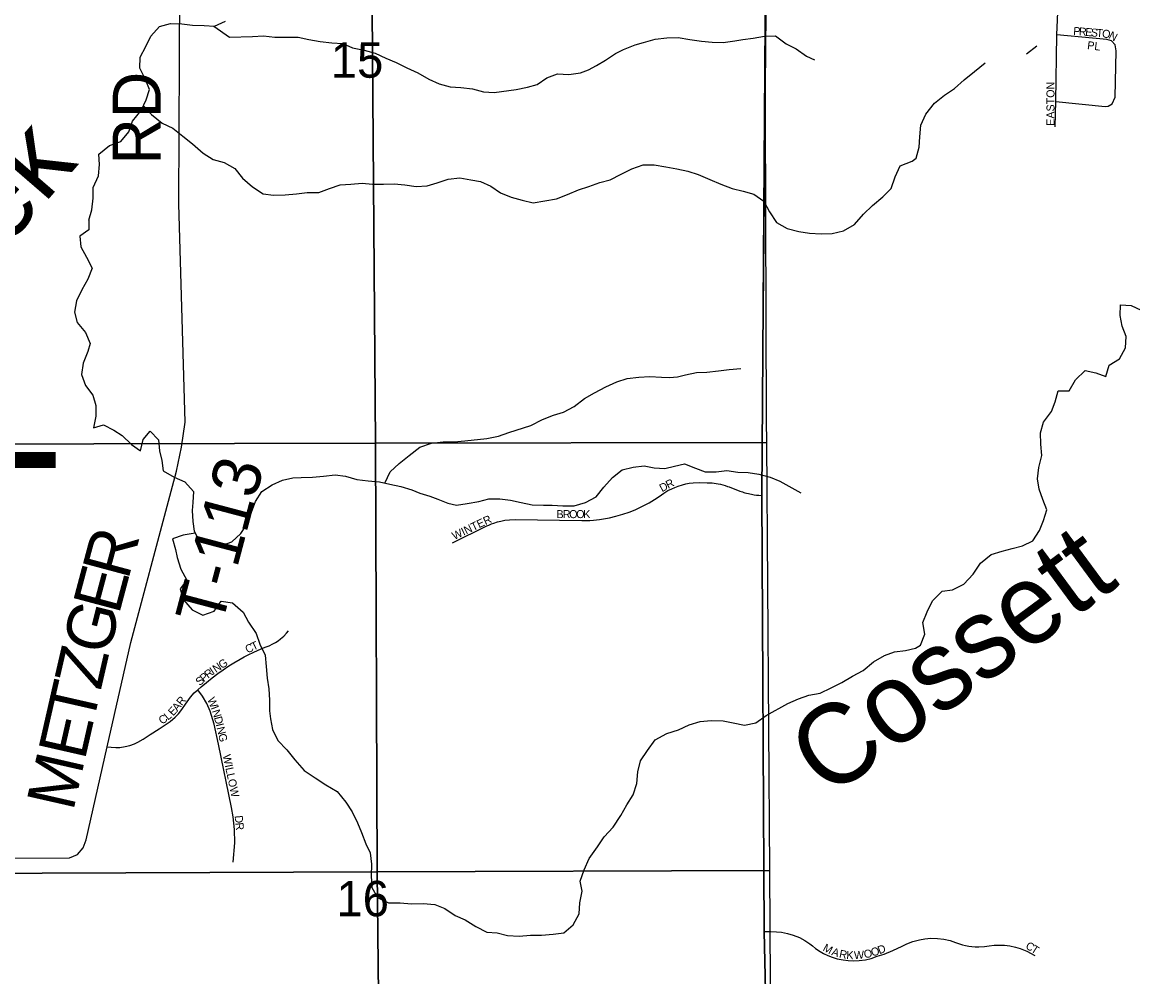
# Model space of a CAD drawing. Extents: x 1985906 to 2277390, y 930619 to 1324581.
# Drawn here: x 2134931 to 2141868, y 1173843 to 1179804 of the extents above; entities that cross this region are included whole.
import ezdxf

# ---------------------------------------------------------------- set-up
doc = ezdxf.new("R2010")
doc.units = 0
for name, color, linetype in [('GM_X_County_Road', 7, 'Continuous'), ('GM_X_Minor_River', 7, 'Continuous'), ('GM_X_Minor_River_Text', 7, 'Continuous'), ('GM_X_Section', 7, 'Continuous'), ('GM_X_Section_Text', 7, 'Continuous'), ('GM_X_Township', 7, 'Continuous'), ('GM_X_Township_Road', 7, 'Continuous'), ('GM_X_Township_Road_Text', 7, 'Continuous'), ('GM_X_Township_Subdivision', 7, 'Continuous'), ('GM_X_Township_Subdivision_Text', 7, 'Continuous'), ('GM_X_Township_Text', 7, 'Continuous')]:
    doc.layers.add(name, color=color, linetype=linetype)

msp = doc.modelspace()

# ---------------------------------------------------------------- linework, layer by layer
at = {"layer": 'GM_X_County_Road'}
msp.add_lwpolyline([(2139668, 1166481.9), (2139668.5, 1166493.7), (2139656.8, 1167688.3), (2139644.7, 1169748.4), (2139611.5, 1172078.9), (2139566.5, 1174124.8), (2139551.5, 1176849.1), (2139580.5, 1180100.5)], dxfattribs=at)
at = {"layer": 'GM_X_Minor_River'}
for points in [[(2135347, 1178568.7), (2135365.4, 1178633), (2135373.8, 1178705.2), (2135374.1, 1178771.5), (2135408.6, 1178843.6), (2135415, 1178915.9), (2135409.3, 1178980.2), (2135475.7, 1179034.1), (2135548.1, 1179059.8), (2135596.5, 1179119.8), (2135620.9, 1179186), (2135675.4, 1179252), (2135705.8, 1179320.1), (2135726.2, 1179384.3), (2135698.4, 1179450.7), (2135666.7, 1179517.2), (2135669, 1179585.5), (2135703.5, 1179651.6), (2135733.9, 1179717.7), (2135788.3, 1179777.7), (2135858.6, 1179795.4), (2135928.8, 1179793), (2135994.9, 1179784.6), (2136067.1, 1179784.2), (2136133.3, 1179779.8), (2136201.6, 1179809.5)], [(2136128.8, 1179779.1), (2136225.2, 1179711), (2136369.6, 1179714.2), (2136437.9, 1179719.8), (2136510, 1179711.4), (2136654.4, 1179710.6), (2136722.5, 1179696.2), (2136792.7, 1179683.7), (2136864.8, 1179675.3), (2136933, 1179670.9), (2136995, 1179644.4), (2137067.2, 1179630), (2137135.3, 1179611.5), (2137203.3, 1179579), (2137267.3, 1179552.5), (2137333.4, 1179520), (2137401.4, 1179487.5), (2137471.4, 1179449), (2137535.4, 1179418.5), (2137603.5, 1179400), (2137671.7, 1179395.6), (2137743.9, 1179387.2), (2137812, 1179368.7), (2137880.1, 1179364.3), (2138016.6, 1179383.7), (2138086.9, 1179397.3), (2138147.1, 1179415.1), (2138207.5, 1179456.9), (2138273.8, 1179480.7), (2138346, 1179478.3), (2138418.3, 1179487.9), (2138468.5, 1179505.7), (2138518.8, 1179533.6), (2138575.1, 1179567.4), (2138637.5, 1179609.2), (2138687.7, 1179633.1), (2138760.1, 1179662.8), (2138812.3, 1179676.6), (2138884.6, 1179698.3), (2138956.8, 1179705.9), (2139029.1, 1179707.5), (2139101.2, 1179695.1), (2139173.3, 1179684.6), (2139241.5, 1179680.2), (2139309.7, 1179677.8), (2139381.9, 1179687.5), (2139432.1, 1179695.2), (2139496.4, 1179704.9), (2139568.6, 1179716.6), (2139636.8, 1179718.2), (2139702.8, 1179669.6), (2139764.8, 1179637.2), (2139830.7, 1179592.6), (2139880.7, 1179568.2)], [(2141269.4, 1179654.7), (2141203.4, 1179604.5)], [(2140489.6, 1178936.4), (2140514.2, 1178954.5), (2140534.2, 1179022.7), (2140538.1, 1179088.8), (2140544, 1179161), (2140576, 1179229.1), (2140629.9, 1179297.3), (2140691.8, 1179347.5), (2140753.8, 1179389.7), (2140813.7, 1179443.8), (2140879.6, 1179496), (2140945.6, 1179550.2)], [(2135687.6, 1179284.1), (2135739.4, 1179227.5), (2135805.4, 1179172.9), (2135871.4, 1179142.4), (2135935.3, 1179091.8), (2135995.3, 1179045.3), (2136061.2, 1178986.7), (2136123.1, 1178946.2), (2136193.2, 1178927.7), (2136259.2, 1178891.2), (2136307.1, 1178830.6), (2136369, 1178776.1), (2136436.9, 1178731.5), (2136501.1, 1178723.1), (2136573.3, 1178726.7), (2136645.5, 1178732.3), (2136711.7, 1178740), (2136783.9, 1178739.6), (2136850.3, 1178765.4), (2136916.6, 1178789.1), (2136984.8, 1178792.8), (2137055, 1178798.4), (2137119.1, 1178792), (2137187.3, 1178791.6), (2137255.5, 1178795.3), (2137321.7, 1178788.9), (2137391.8, 1178778.4), (2137460, 1178782.1), (2137522.3, 1178799.8), (2137592.6, 1178823.5), (2137664.9, 1178831.2), (2137733, 1178818.7), (2137793.1, 1178808.4), (2137859.2, 1178779.9), (2137919.1, 1178737.4), (2137985.2, 1178710.9), (2138053.3, 1178692.4), (2138123.4, 1178676), (2138195.6, 1178687.6), (2138267.9, 1178701.3), (2138338.2, 1178727), (2138406.6, 1178756.8), (2138470.9, 1178778.5), (2138539.2, 1178802.2), (2138603.4, 1178819.9), (2138671.8, 1178855.7), (2138738.2, 1178887.5), (2138810.5, 1178913.2), (2138878.7, 1178912.8), (2138950.8, 1178900.4), (2139021, 1178888), (2139089.1, 1178873.5), (2139153.2, 1178853.1), (2139225.2, 1178822.5), (2139295.2, 1178792), (2139365.3, 1178765.5), (2139433.4, 1178749.1), (2139501.5, 1178730.6), (2139563.5, 1178686.1), (2139599.2, 1178619.6), (2139643, 1178553.1), (2139709, 1178516.5), (2139781.1, 1178496.1), (2139849.3, 1178485.6), (2139921.5, 1178483.2), (2139989.7, 1178484.8), (2140061.9, 1178500.5), (2140130.3, 1178540.3), (2140186.8, 1178604.3), (2140241.2, 1178660.2), (2140305.7, 1178714.1), (2140358.1, 1178766.1), (2140384.5, 1178838.2), (2140415, 1178906.4), (2140489.6, 1178936.4)], [(2135347.1, 1178568.8), (2135346.8, 1178506.5), (2135290.4, 1178468.6), (2135298.1, 1178400.3), (2135333.9, 1178335.8), (2135367.6, 1178267.3), (2135341.2, 1178199.2), (2135304.8, 1178133.1), (2135270.3, 1178063), (2135258, 1177992.7), (2135275.7, 1177928.3), (2135327.5, 1177865.8), (2135355.3, 1177797.3), (2135341, 1177747.2), (2135312.5, 1177675), (2135302.1, 1177604.8), (2135325.9, 1177536.3), (2135371.7, 1177475.8), (2135391.4, 1177409.4), (2135391.1, 1177343.1), (2135376.7, 1177270.9), (2135439, 1177290.6), (2135503, 1177256.1), (2135555, 1177223.7), (2135614.8, 1177167.1), (2135670.8, 1177126.6), (2135687.2, 1177198.9), (2135731.6, 1177250.8), (2135783.5, 1177196.3), (2135789.1, 1177128), (2135802.9, 1177067.7), (2135812.6, 1177003.3), (2135880.6, 1176962.8), (2135946.6, 1176934.3), (2136000.5, 1176873.7), (2135996.1, 1176805.4), (2135993.9, 1176755.2), (2135997.5, 1176686.9), (2136005.2, 1176626.6), (2136039, 1176560.1), (2136107.1, 1176541.7), (2136175.3, 1176535.3), (2136241.6, 1176559), (2136296, 1176610.9), (2136340.4, 1176677), (2136362.8, 1176745.1), (2136389.2, 1176811.3), (2136427.7, 1176873.4), (2136492, 1176915.2), (2136556.4, 1176945), (2136622.6, 1176958.7), (2136672.8, 1176960.4), (2136745, 1176962), (2136813.2, 1176969.7), (2136885.5, 1176977.3), (2136951.6, 1176968.9), (2137021.7, 1176948.4), (2137091.8, 1176940), (2137162, 1176933.6), (2137228.1, 1176919.2), (2137296.2, 1176904.7), (2137364.3, 1176884.2), (2137414.4, 1176863.9), (2137476.5, 1176843.5), (2137526.5, 1176825.1), (2137590.6, 1176800.6), (2137644.6, 1176788.3), (2137710.9, 1176798), (2137783.1, 1176811.6), (2137845.4, 1176827.3), (2137913.6, 1176827), (2137981.7, 1176818.6), (2138047.9, 1176804.1), (2138116, 1176789.7), (2138188.2, 1176787.3), (2138242.3, 1176787), (2138308.5, 1176784.6), (2138378.7, 1176784.2), (2138449, 1176803.9), (2138515.3, 1176839.7), (2138563.8, 1176899.7), (2138618.2, 1176961.7), (2138678.6, 1177009.6), (2138746.9, 1177025.3), (2138815.1, 1177032.9), (2138879.3, 1177020.5), (2138945.4, 1177016.1), (2139005.7, 1177031.9), (2139067.9, 1177045.6), (2139136, 1177019.1), (2139198, 1176996.6), (2139266.2, 1176996.3), (2139332.4, 1177003.9), (2139400.6, 1176993.5), (2139464.7, 1176991.2), (2139532.9, 1176980.7), (2139603, 1176962.3), (2139663, 1176937.8), (2139795, 1176864.8)], [(2140510.6, 1175895.9), (2140542.9, 1175914), (2140568.8, 1175982.2), (2140556.7, 1176054.3), (2140582.7, 1176122.5), (2140616.6, 1176190.7), (2140676.5, 1176250.9), (2140742.5, 1176258.9), (2140812.4, 1176295.1), (2140870.3, 1176357.3), (2140916.3, 1176425.5), (2140984.2, 1176479.6), (2141052.2, 1176499.8), (2141114.1, 1176517.8), (2141178.1, 1176533.9), (2141244, 1176566.1), (2141286, 1176630.2), (2141309.9, 1176692.4), (2141331.8, 1176758.6), (2141305.8, 1176822.7), (2141283.7, 1176888.8), (2141271.7, 1176952.9), (2141281.6, 1177023.1), (2141299.5, 1177097.2), (2141293.5, 1177169.4), (2141291.4, 1177239.5), (2141309.4, 1177305.7), (2141359.3, 1177371.9), (2141383.2, 1177434.1), (2141401.2, 1177502.2), (2141471.1, 1177502.3), (2141509.1, 1177570.5), (2141571, 1177628.6), (2141637, 1177614.7), (2141699, 1177590.7), (2141720.9, 1177662.8), (2141784.8, 1177701), (2141822.8, 1177771.2), (2141826.7, 1177841.3), (2141800.7, 1177905.4), (2141788.6, 1177971.6), (2141790.6, 1178039.7), (2141858.5, 1178035.8), (2141920.5, 1178005.8)], [(2137196.6, 1176926), (2137230.5, 1176995.5), (2137284.9, 1177047.4), (2137347.4, 1177097.3), (2137415.8, 1177151.1), (2137488.1, 1177174.8), (2137560.4, 1177182.5), (2137628.6, 1177184.1), (2137696.8, 1177189.8), (2137833.2, 1177205.1), (2137905.5, 1177218.7), (2137971.8, 1177242.5), (2138108.4, 1177285.9), (2138180.8, 1177323.7), (2138249.1, 1177349.4), (2138311.4, 1177369.2), (2138377.8, 1177405), (2138444.2, 1177454.8), (2138506.5, 1177488.6), (2138576.9, 1177526.4), (2138645.3, 1177558.2), (2138709.6, 1177579.9), (2138781.8, 1177587.6), (2138852, 1177591.2), (2138924.2, 1177586.8), (2138974.3, 1177584.5), (2139024.5, 1177590.2), (2139074.7, 1177602), (2139143, 1177615.7), (2139207.2, 1177619.3), (2139279.4, 1177627), (2139347.6, 1177634.6), (2139419.9, 1177642.3)], [(2136012, 1176614.2), (2135936.9, 1176600.9), (2135870.6, 1176577.1), (2135888.3, 1176510.7), (2135900.1, 1176460.4), (2135921.8, 1176388), (2135959.6, 1176319.5), (2135917.2, 1176265.5), (2135938.9, 1176197.1), (2135992.8, 1176134.5), (2136058.8, 1176102), (2136131.1, 1176125.7), (2136173.5, 1176187.7), (2136245.7, 1176177.3), (2136311.6, 1176120.7), (2136345.4, 1176058.2), (2136393.1, 1175985.6), (2136414.9, 1175919.2), (2136448.6, 1175850.8), (2136454.3, 1175780.4), (2136462, 1175708), (2136471.7, 1175641.7), (2136475.3, 1175569.4), (2136475, 1175503.1), (2136482.7, 1175452.8), (2136494.4, 1175386.4), (2136528.2, 1175318), (2136584.1, 1175259.4), (2136633.9, 1175196.8), (2136691.7, 1175130.2), (2136761.7, 1175085.6), (2136827.7, 1175041.1), (2136897.7, 1175000.5), (2136953.5, 1174933.9), (2136991.3, 1174873.5), (2137025, 1174805), (2137050.8, 1174744.6), (2137078.5, 1174674.1), (2137104.3, 1174617.7), (2137114, 1174545.3), (2137111.6, 1174473), (2137115.3, 1174400.7), (2137151.1, 1174338.2), (2137219.1, 1174305.7), (2137291.3, 1174305.3), (2137363.5, 1174298.9), (2137435.7, 1174300.5), (2137507.8, 1174294.1), (2137571.9, 1174269.6), (2137635.9, 1174225.1), (2137697.9, 1174198.6), (2137763.9, 1174156.1), (2137833.9, 1174121.5), (2137898.1, 1174117.1), (2137962.2, 1174100.7), (2138034.3, 1174096.3), (2138106.6, 1174101.9), (2138174.8, 1174103.6), (2138247, 1174109.2), (2138315.2, 1174116.8), (2138371.6, 1174166.8), (2138410.1, 1174236.8), (2138414.4, 1174305.1), (2138428.8, 1174377.4), (2138417.1, 1174439.7), (2138441.5, 1174509.9), (2138472, 1174582), (2138524.5, 1174654.1), (2138566.9, 1174716.1), (2138621.4, 1174778.1), (2138669.9, 1174850.1), (2138708.3, 1174916.2), (2138746.7, 1174980.2), (2138771.1, 1175050.4), (2138775.5, 1175122.7), (2138793.9, 1175190.9), (2138836.4, 1175257), (2138884.8, 1175323), (2138957.2, 1175362.8), (2139029.5, 1175384.5), (2139097.9, 1175416.2), (2139166.2, 1175438), (2139234.4, 1175443.6), (2139308.6, 1175441.2), (2139372.7, 1175428.8), (2139442.8, 1175414.3), (2139513.1, 1175428), (2139577.5, 1175473.8), (2139714.3, 1175549.4), (2139780.6, 1175579.2), (2139844.9, 1175600.9), (2139915.2, 1175614.6), (2139983.5, 1175646.4), (2140049.9, 1175680.2), (2140116.2, 1175720), (2140184.6, 1175755.8), (2140249.1, 1175809.6), (2140317.4, 1175849.4), (2140379.7, 1175871.2), (2140448, 1175880.8), (2140510.6, 1175896)]]:
    msp.add_lwpolyline(points, dxfattribs=at)
at = {"layer": 'GM_X_Section'}
for points in [[(2137116.7, 1179878.2), (2137137.1, 1177174.3), (2134496.5, 1177169.7), (2134481.4, 1179851.9)], [(2139570, 1179882.9), (2139578.7, 1177314.5), (2139579.9, 1177178.5), (2137137.1, 1177174.3), (2137116.7, 1179878.2)], [(2137137.1, 1177174.3), (2137148.8, 1174497.5), (2134532.2, 1174488.2), (2134496.5, 1177169.7)], [(2139579.9, 1177178.5), (2139599.2, 1174506.3), (2137148.8, 1174497.5), (2137137.1, 1177174.3)], [(2137148.8, 1174497.5), (2137179.2, 1171609.7), (2134570.4, 1171622.4), (2134532.2, 1174488.2)], [(2139599.2, 1174506.3), (2139614.4, 1172069.9), (2139617.3, 1171597.8), (2137179.2, 1171609.7), (2137148.8, 1174497.5)]]:
    msp.add_lwpolyline(points, close=True, dxfattribs=at)
at = {"layer": 'GM_X_Township'}
for points in [[(2139644.7, 1169748.4), (2139611.5, 1172078.9), (2139566.5, 1174124.9), (2139551.5, 1176849.1), (2139574.3, 1180104.3), (2139561.5, 1182741.2), (2139581.4, 1183078.2), (2139560.8, 1184019.4), (2139556, 1185150.7), (2139556, 1185444), (2139503.5, 1186666), (2139494.6, 1188225.5), (2139496.8, 1188359.9), (2139502.2, 1190793.3), (2139549.1, 1193676.6), (2140581.8, 1193696.4), (2144321.2, 1193786.8), (2145028.4, 1193800.8), (2151106.9, 1193912.6)], [(2117908.3, 1193445.4), (2126053.1, 1193488.1), (2129443.2, 1193492.7), (2134076.1, 1193549.4), (2139549.1, 1193676.6), (2139502.2, 1190793.3), (2139496.8, 1188359.9), (2139494.6, 1188225.5), (2139503.5, 1186666), (2139556, 1185444), (2139556, 1185150.7), (2139560.8, 1184019.4), (2139581.4, 1183078.2), (2139561.5, 1182741.2), (2139574.3, 1180104.3), (2139551.5, 1176849.1), (2139566.5, 1174124.9), (2139611.5, 1172078.9), (2139644.7, 1169748.4)]]:
    msp.add_lwpolyline(points, dxfattribs=at)
at = {"layer": 'GM_X_Township_Road'}
for points in [[(2135277.4, 1174606.2), (2135313.1, 1174647.8), (2135330.9, 1174698.4), (2135462.8, 1175279), (2135610.5, 1175929.8), (2135845.5, 1176813.2), (2135896.1, 1177000.6), (2135925.8, 1177149.3), (2135949.6, 1177307), (2135909.4, 1178670.4), (2135915.3, 1180020.3)], [(2134376.1, 1174582.4), (2135226.8, 1174585.3), (2135277.4, 1174606.2)]]:
    msp.add_lwpolyline(points, dxfattribs=at)
at = {"layer": 'GM_X_Township_Subdivision'}
for points in [[(2141383.9, 1179150.2), (2141388, 1179309.5), (2141394.2, 1179724.1), (2141411.8, 1180148)], [(2141388, 1179309.5), (2141695.7, 1179277.9), (2141713.5, 1179280.2), (2141738.5, 1179294.5), (2141757, 1179336.5), (2141763.7, 1179625.2), (2141758.1, 1179662.6), (2141735, 1179688.1), (2141705.3, 1179696.8), (2141394.2, 1179724.1)], [(2137618.9, 1176553.3), (2137833.9, 1176658.1), (2137845.2, 1176663.4), (2137861.9, 1176670.5), (2137877.7, 1176676.4), (2137899.2, 1176683.2), (2137920.7, 1176688.7), (2137946.8, 1176693.8), (2137975.7, 1176697.3), (2138010.3, 1176698.8), (2138427.5, 1176691.3), (2138448.4, 1176691.7), (2138476.7, 1176693), (2138500.6, 1176694.8), (2138536.7, 1176698.8), (2138561.2, 1176702.4), (2138598.5, 1176709.3), (2138639.4, 1176718.8), (2138683.7, 1176731.6), (2138721.9, 1176744.8), (2138758.8, 1176759.5), (2138802.2, 1176779.3), (2138847.2, 1176803.2), (2138897.9, 1176834.4), (2138924.2, 1176852.6), (2138938.4, 1176862.5), (2138951, 1176870.5), (2138964.7, 1176878.6), (2138988.9, 1176891), (2139007.5, 1176899.2), (2139028.8, 1176907.3), (2139056.1, 1176915.6), (2139075.4, 1176920.3), (2139097.8, 1176924.5), (2139123, 1176927.6), (2139160.2, 1176929.2), (2139210.2, 1176928.4), (2139219.6, 1176928.1), (2139230.9, 1176927.5), (2139241.7, 1176926.6), (2139253.1, 1176925.4), (2139264.7, 1176923.8), (2139278.4, 1176921.4), (2139293.7, 1176918.2), (2139306.9, 1176914.9), (2139321.1, 1176910.8), (2139337.2, 1176905.5), (2139347.7, 1176901.6), (2139414, 1176876.1), (2139421.4, 1176873.4), (2139430.1, 1176870.3), (2139437.7, 1176867.9), (2139445.4, 1176865.5), (2139455.4, 1176862.7), (2139466.7, 1176859.9), (2139476.2, 1176857.8), (2139486.5, 1176855.7), (2139494.8, 1176854.4), (2139503.8, 1176853), (2139517.2, 1176851.4), (2139531.7, 1176850.2), (2139551.5, 1176849.1)], [(2135462.8, 1175279), (2135486.6, 1175275.8), (2135515.2, 1175274.4), (2135541.4, 1175275.6), (2135574.7, 1175280.4), (2135603.3, 1175287.6), (2135632.3, 1175298.3), (2135654.6, 1175308.8), (2135686.1, 1175327.6), (2135731.1, 1175356.2), (2135786.9, 1175391.6), (2135855.8, 1175437.8), (2135885.8, 1175463.9), (2135906.9, 1175485.8), (2135928.5, 1175512.2), (2135951.3, 1175545.2), (2135982.7, 1175589), (2136006.2, 1175615.3), (2136027.4, 1175635.6), (2136049.3, 1175653.9), (2136081.6, 1175680.5), (2136118.3, 1175710.3), (2136153.2, 1175737), (2136185.8, 1175760.2), (2136221.8, 1175784.2), (2136253.9, 1175804.1), (2136291.9, 1175826.1), (2136317.5, 1175840), (2136347.5, 1175855.3), (2136373.7, 1175867.9), (2136404.9, 1175882), (2136449, 1175900.5), (2136473.2, 1175910.5), (2136496, 1175921.1), (2136512.8, 1175930.5), (2136529.4, 1175941.2), (2136544.8, 1175952.6), (2136565, 1175970.2), (2136583, 1175988.8), (2136594.4, 1176002.5)], [(2136249.7, 1174558.8), (2136259.1, 1174679.4), (2136257, 1174763.2), (2136248.6, 1174842.2), (2136238.4, 1174899.6), (2136156.4, 1175294.9), (2136130.4, 1175420.1), (2136106.3, 1175501.2), (2136084.1, 1175549.7), (2136057.9, 1175594.3), (2136027.4, 1175635.6)], [(2139566.5, 1174124.8), (2139606.5, 1174125.6), (2139641.8, 1174124.7), (2139673.4, 1174121.3), (2139711.8, 1174113.7), (2139746.2, 1174103.4), (2139785.5, 1174087.4), (2139818.7, 1174069.8), (2139850.3, 1174048.9), (2139867.4, 1174035.7), (2139887.1, 1174020.3), (2139914.8, 1174001.6), (2139936.4, 1173989.2), (2139963.2, 1173976.2), (2139990.2, 1173965.5), (2140021.6, 1173955.8), (2140057.9, 1173947.9), (2140090.8, 1173943.7), (2140121.6, 1173942.3), (2140158.3, 1173943.8), (2140198.3, 1173949.3), (2140234.2, 1173957.8), (2140271.8, 1173971.4), (2140314.2, 1173984.8), (2140369, 1174006.2), (2140427.6, 1174034.4), (2140457.3, 1174049.1), (2140493.9, 1174063.2), (2140536.1, 1174074.7), (2140569.3, 1174080.3), (2140606.7, 1174083.2), (2140648.9, 1174082.4), (2140687.6, 1174077.6), (2140726.4, 1174068.9), (2140760.8, 1174057.7), (2140779.7, 1174050.8), (2140804.9, 1174043.4), (2140823.1, 1174039.1), (2140843.8, 1174035.2), (2140862.3, 1174032.8), (2140883.5, 1174031), (2140905.9, 1174030.4), (2140941.6, 1174031.9), (2140970.6, 1174035.6), (2141002.1, 1174039.6), (2141034, 1174041), (2141066.4, 1174039.8), (2141100.1, 1174035.8), (2141134.6, 1174028.7), (2141164.9, 1174019.7), (2141205.8, 1174003.2), (2141256.2, 1173974.9)]]:
    msp.add_lwpolyline(points, dxfattribs=at)

# ---------------------------------------------------------------- texts
at = {"layer": 'GM_X_Minor_River_Text'}
for s, height, rotation, p in [('Creek', 500.28, 49.17281, (2134119.9, 1177569)), ('Cossett', 500.26, 36.36573, (2139965.9, 1174949.7))]:
    msp.add_text(s, height=height, rotation=rotation, dxfattribs=at).set_placement(p)
at = {"layer": 'GM_X_Section_Text'}
for s, p in [('15', (2136858.3, 1179457.3)), ('16', (2136893.5, 1174220.7))]:
    msp.add_text(s, height=221, rotation=0.00001, dxfattribs=at).set_placement(p)
at = {"layer": 'GM_X_Township_Road_Text'}
for s, rotation, p in [('RD', 90, (2135796.5, 1178915.2)), ('T-113', 75.16093, (2136175.7, 1176022.8)), ('R', 74.98963, (2135592.6, 1176315.2)), ('E', 75.10722, (2135535, 1176098.5)), ('G', 75.9929, (2135471.4, 1175843.6)), ('Z', 76.99799, (2135421.2, 1175626.3)), ('T', 77.17574, (2135371.5, 1175407.7)), ('E', 77.17323, (2135321.6, 1175188.9)), ('M', 77.17517, (2135249.4, 1174871.4))]:
    msp.add_text(s, height=300, rotation=rotation, dxfattribs=at).set_placement(p)
at = {"layer": 'GM_X_Township_Subdivision_Text'}
for s, rotation, p in [('P', 355.04801, (2141494.4, 1179725.4)), ('R', 355.05536, (2141529.5, 1179722.3)), ('E', 355.04801, (2141568.9, 1179718.9)), ('S', 355.06197, (2141604, 1179715.9)), ('T', 355.04801, (2141639.1, 1179712.9)), ('O', 352.54692, (2141673.6, 1179709.9)), ('N', 331.77325, (2141712.7, 1179705.7)), ('PL', 352.87835, (2141581.1, 1179636.5)), ('EASTON', 90, (2141378.7, 1179157.2)), ('D', 28.77441, (2138928, 1176868.5)), ('R', 26.99951, (2138966.2, 1176889.5)), ('B', 0.07286, (2138268.5, 1176707)), ('R', 0.07286, (2138308.1, 1176707.1)), ('O', 0.08287, (2138347.7, 1176707.1)), ('O', 0.06558, (2138391.7, 1176707.2)), ('K', 0.07126, (2138435.7, 1176707.2)), ('WINTER', 25.60087, (2137630.8, 1176569.7)), ('T', 26.17402, (2136375.6, 1175878.6)), ('C', 24.19674, (2136337.8, 1175861.6)), ('N', 33.65976, (2136141.3, 1175739.6)), ('G', 33.1384, (2136177.8, 1175763.9)), ('S', 41.07541, (2136040.3, 1175657.5)), ('P', 41.05481, (2136066.8, 1175680.6)), ('R', 38.16677, (2136092.8, 1175703.3)), ('I', 34.36895, (2136123.3, 1175727.2)), ('R', 51.10879, (2135928.3, 1175532.2)), ('W', 293.46572, (2136085.9, 1175575)), ('E', 45.95207, (2135873, 1175468.5)), ('A', 51.60283, (2135901, 1175497.8)), ('I', 291.06263, (2136108.5, 1175523.1)), ('N', 286.83115, (2136116.1, 1175503.5)), ('C', 33.73048, (2135804.1, 1175416.5)), ('L', 39.80166, (2135841.6, 1175442)), ('D', 284.99056, (2136128.7, 1175461.8)), ('I', 283.54846, (2136140, 1175419.6)), ('N', 283.02903, (2136145.1, 1175398.3)), ('G', 282.98643, (2136155, 1175355.5)), ('WILLOW', 281.97643, (2136183.3, 1175225.6)), ('D', 275.29735, (2136258.3, 1174848.4)), ('R', 276.33145, (2136262.5, 1174803.6)), ('M', 331.41426, (2139927.6, 1174008.6)), ('C', 330.27319, (2141193.6, 1174022.4)), ('A', 341.45777, (2139982.7, 1173979.5)), ('R', 348.52964, (2140030.9, 1173963.8)), ('K', 357.13312, (2140077.8, 1173954.9)), ('W', 3.11591, (2140127.5, 1173952.7)), ('O', 13.12753, (2140194, 1173957.2)), ('O', 18.75489, (2140242, 1173968.6)), ('D', 20.75142, (2140285.5, 1173983.4)), ('T', 327.91643, (2141227.6, 1174003))]:
    msp.add_text(s, height=50, rotation=rotation, dxfattribs=at).set_placement(p)
at = {"layer": 'GM_X_Township_Text'}
msp.add_text('LIVERPOOL', height=900, rotation=0.00001, dxfattribs=at).set_placement((2128357.7, 1177020.9))

doc.saveas('drawing.dxf')
